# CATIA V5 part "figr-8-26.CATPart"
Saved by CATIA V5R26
Part number: Part3
Bounding box of the stored display mesh (mm): x -50 to 50, y -40 to 40, z 0 to 36
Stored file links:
  D:\_Deepak\CATIA\CATIA V5-6R2016_Deepak\Resources\Part files\Partfiles\c08_catia_v5_6r2016_prt\figr-8-26.CATPart
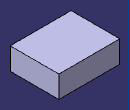
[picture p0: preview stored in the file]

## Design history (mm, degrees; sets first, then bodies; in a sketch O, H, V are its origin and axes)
Body1 (main body)
  Sketch1 on xy-plane, origin (0, 0, 0), H (1, 0, 0), V (0, 1, 0)
    line L1 (-50, 40) -> (50, 40)
    line L2 (50, 40) -> (50, -40)
    line L3 (50, -40) -> (-50, -40)
    line L4 (-50, -40) -> (-50, 40)
    horizontal: L1 H, L3 H
    vertical: L2 V, L4 V
  Pad1: profile Sketch1, direction (0, 0, 1), length 36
